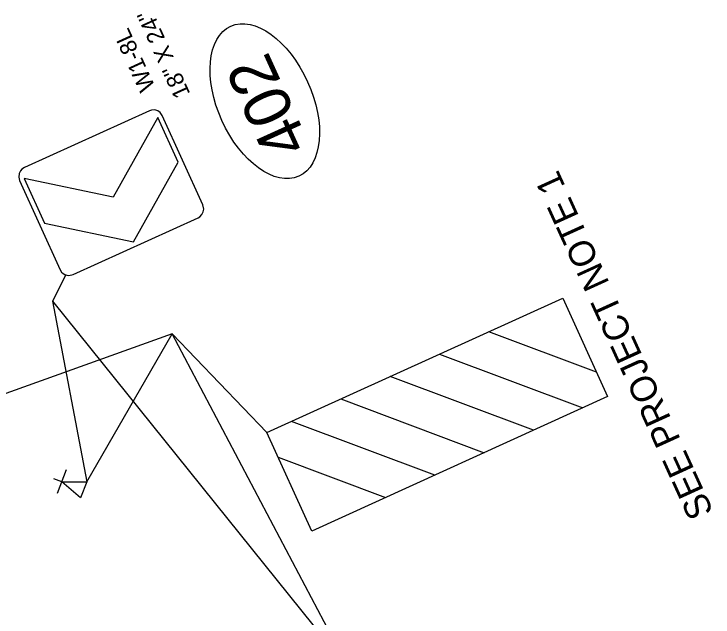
# Model space of a CAD drawing. Extents: x 2093420 to 2100301, y 676254 to 688367.
# Drawn here: x 2096798.3 to 2096986.5, y 684297.6 to 684460 of the extents above; entities that cross this region are included whole.
import ezdxf

# ---------------------------------------------------------------- set-up
doc = ezdxf.new("R2010")
doc.units = 0
for name, color, linetype in [('Default', 7, 'Continuous'), ('Exist Sign E Bridge Marker Right', 7, 'Continuous'), ('Prop DSN Text', 7, 'Continuous')]:
    doc.layers.add(name, color=color, linetype=linetype)

msp = doc.modelspace()

# ---------------------------------------------------------------- linework, layer by layer
at = {"layer": 'Default'}
for p, q in [((2096825.01, 684410.66), (2096825.01, 684410.66)), ((2096808.69, 684382.64), (2096817.86, 684334)), ((2096840.83, 684373.86), (2096763.09, 684345.98)), ((2096817.86, 684334), (2096840.83, 684373.86)), ((2096866.35, 684347.28), (2096840.83, 684373.86)), ((2096889.04, 684282.73), (2096840.83, 684373.86)), ((2096812.35, 684337.23), (2096809.9, 684330.88)), ((2096811.12, 684334.03), (2096808.96, 684334.86)), ((2096816.21, 684329.74), (2096811.12, 684334.03)), ((2096811.12, 684334.03), (2096817.86, 684334)), ((2096817.86, 684334), (2096816.21, 684329.74))]:
    msp.add_line(p, q, dxfattribs=at)
for points in [[(2096834.72, 684433.92), (2096801.1, 684418.63), (2096800.38, 684418.17), (2096800.03, 684417.73), (2096799.7, 684417.07), (2096799.57, 684416.08), (2096799.79, 684415.14), (2096810.71, 684391.12), (2096811.11, 684390.5), (2096811.51, 684390.14), (2096811.99, 684389.85), (2096812.54, 684389.64), (2096813.08, 684389.58), (2096814.2, 684389.82), (2096847.82, 684405.11), (2096848.34, 684405.39), (2096848.88, 684405.98), (2096849.22, 684406.67), (2096849.37, 684407.46), (2096849.13, 684408.6), (2096838.21, 684432.61), (2096837.62, 684433.46), (2096837.02, 684433.86), (2096836.24, 684434.13), (2096835.3, 684434.07), (2096834.72, 684433.92)], [(2096812.27, 684389.75), (2096808.69, 684382.64), (2096889.04, 684282.73)]]:
    msp.add_lwpolyline(points, dxfattribs=at)
msp.add_lwpolyline([(2096837.02, 684432.07), (2096825.01, 684410.66), (2096801, 684415.69), (2096806.46, 684403.68), (2096830.47, 684398.65), (2096842.48, 684420.06)], close=True, dxfattribs=at)
msp.add_ellipse((2096865.8, 684436.49), major_axis=(9.17, -20.19), ratio=0.571429, dxfattribs=at)
at = {"layer": 'Exist Sign E Bridge Marker Right'}
for p, q in [((2096866.35, 684347.28), (2096946.01, 684383.51)), ((2096946.01, 684383.51), (2096958.09, 684356.96)), ((2096955.07, 684363.59), (2096926.09, 684374.45)), ((2096912.82, 684368.41), (2096951.45, 684353.94)), ((2096938.17, 684347.9), (2096899.54, 684362.37)), ((2096958.09, 684356.96), (2096878.43, 684320.72)), ((2096886.26, 684356.34), (2096924.9, 684341.86)), ((2096911.62, 684335.82), (2096872.99, 684350.3)), ((2096878.43, 684320.72), (2096866.35, 684347.28)), ((2096869.37, 684340.64), (2096898.34, 684329.78))]:
    msp.add_line(p, q, dxfattribs=at)

# ---------------------------------------------------------------- texts
at = {"layer": 'Default'}
for s, height, rotation, p in [('402', 12.516, 114.4239, (2096877.98, 684424.79)), ('SEE PROJECT NOTE 1', 7, 114.4888, (2096986.72, 684325.95))]:
    msp.add_text(s, height=height, rotation=rotation, dxfattribs=at).set_placement(p)
at = {"layer": 'Prop DSN Text'}
for s, p in [("18'' X 24''", (2096845.8, 684438.51)), ('W1-8L', (2096836.38, 684440.34))]:
    msp.add_text(s, height=4.5, rotation=114.458, dxfattribs=at).set_placement(p)

doc.saveas('drawing.dxf')
